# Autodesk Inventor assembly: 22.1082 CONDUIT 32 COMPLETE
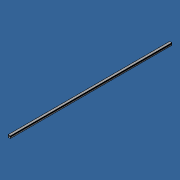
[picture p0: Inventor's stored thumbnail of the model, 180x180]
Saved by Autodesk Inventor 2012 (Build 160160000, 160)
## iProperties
Created: 2016-03
Part Number: 22.1082 CONDUIT 32 COMPLETE
Document SubType Name: Assembly
Designer: Admin
Author: Admin
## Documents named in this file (3)
- C:\Andys Backup Data\ANDY'S INVENTOR\INVENTOR LIBRARIES\PARTS LIBRARY\ELECTRICAL INSTALLATION\22.1082 CONDUIT 32 COMPLETE.iam
- C:\Andys Backup Data\ANDY'S INVENTOR\INVENTOR LIBRARIES\PARTS LIBRARY\ELECTRICAL INSTALLATION\22.1082 CONDUIT 32 BOTTOM.ipt
- C:\Andys Backup Data\ANDY'S INVENTOR\INVENTOR LIBRARIES\PARTS LIBRARY\ELECTRICAL INSTALLATION\22.1082 CONDUIT 32 TOP.ipt
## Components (2 placed, 2 different names)
1. 22.1082 CONDUIT 32 BOTTOM:1 — Flush:2, Flush:3, Mate:1
2. 22.1082 CONDUIT 32 TOP:1 — Flush:2, Flush:3, Mate:1
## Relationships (3: Flush 2, Mate 1)
- Flush:2: 22.1082 CONDUIT 32 BOTTOM:1 ↔ 22.1082 CONDUIT 32 TOP:1
- Flush:3: 22.1082 CONDUIT 32 BOTTOM:1 ↔ 22.1082 CONDUIT 32 TOP:1
- Mate:1: 22.1082 CONDUIT 32 BOTTOM:1 ↔ 22.1082 CONDUIT 32 TOP:1
